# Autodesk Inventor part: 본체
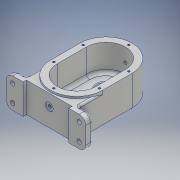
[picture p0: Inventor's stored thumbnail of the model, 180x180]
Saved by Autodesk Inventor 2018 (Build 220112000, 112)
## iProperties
Created: 2021-05
Part Number: 본체
Material: 알루미늄 6061
Document SubType Name: Modeling
Designer: Admin
Density: 2.7 g/cm^3
Appearance: 알루미늄 - 평지
Mass: 756.275 g
Surface Area: 582.942 cm^2
Volume: 280.102 cm^3
Author: Admin
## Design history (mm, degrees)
sketch "스케치1"
  geometry: L1 (-56, 0)-(56, 0) reference; L2 (0, -87.5)-(0, 87.5) reference; L3 (0, 22.5)-(0, -22.5); L4 (-40, 22.5)-(-40, -22.5); L5 (40, -22.5)-(40, 22.5); A1 r 40 centre (0, 22.5) between (40, 22.5) and (-40, 22.5); A2 r 40 centre (0, -22.5) between (-40, -22.5) and (40, -22.5); 2 further points
  constraints: 8 end point, 4 point on circle, 4 tangent, 2 centre point, 2 point on line, 1 coincident, 1 midpoint, 1 parallel
  dimensions: "d0" = 80 diameter of A2; "d1" = 45 distance of L5.start L5.end
extrude "돌출1" new body sketch "스케치1" distance "d2" = 49; taper "d3" = 0 deg
node "작업 평면1"
sketch "스케치2"
  geometry: L1 (61, -3)-(-61, -3); L2 (-61, -3)-(-61, -49); L3 (-61, -49)-(61, -49); L4 (61, -49)-(61, -3); L5 (-40, -49)-(40, -49) reference; L6 (85.4, 0)-(-85.4, 0) reference; L7 (0, -58.8)-(0, 9.8) reference; L8 (40, 0)-(-40, 0) reference; 2 further points
  constraints: 8 end point, 2 midpoint, 2 parallel, 1 horizontal, 1 perpendicular, 1 other
  dimensions: "d5" = 46 distance of L3.end L1.start; "d6" = 122 distance of L1.start L1.end
extrude "돌출2" join sketch "스케치2" distance "d7" = 10; taper "d8" = 0 deg
sketch "스케치3"
  geometry: L1 (-61, 3)-(61, 3) reference; L2 (-61, 49)-(-61, 3) reference; L3 (61, 49)-(-61, 49) reference; L4 (61, 3)-(61, 49) reference; L5 (0, 58.8)-(0, -9.8) reference; L6 (61, 49)-(-61, 49) reference; L7 (-40, 3)-(40, 3); L8 (40, 3)-(40, 49); L9 (40, 49)-(-40, 49); L10 (-40, 49)-(-40, 3); 1 further point
  constraints: 8 end point, 2 parallel, 2 point on line, 1 horizontal, 1 perpendicular, 1 other
  dimensions: "d9" = 80 distance between parallel lines of L8 L10
extrude "돌출3" join sketch "스케치3" distance "d10" = 37; taper "d11" = 0 deg
sketch "스케치4"
  geometry: L1 (-40, 22.5)-(-40, -22.5) reference; L2 (40, -22.5)-(40, 22.5) reference; L3 (0, 22.5)-(0, -22.5); L4 (-30, 22.5)-(-30, -22.5); L5 (30, -22.5)-(30, 22.5); A1 r 40 centre (0, -22.5) between (-40, -22.5) and (40, -22.5) reference; A2 r 40 centre (0, 22.5) between (40, 22.5) and (-40, 22.5) reference; A3 r 30 centre (0, 22.5) between (30, 22.5) and (-30, 22.5); A4 r 30 centre (0, -22.5) between (-30, -22.5) and (30, -22.5); 2 further points
  constraints: 8 end point, 4 point on circle, 4 tangent, 2 centre point, 1 midpoint, 1 parallel, 1 vertical
  dimensions: "d12" = 60 diameter of A4
extrude "돌출4" cut sketch "스케치4" distance "d13" = 41; taper "d14" = 0 deg
sketch "스케치5"
  geometry: L1 (-30, -22.5)-(-30, 22.5) reference; L2 (30, 22.5)-(30, -22.5) reference; C1 r 14 at (0, 22.5); C2 r 14 at (0, -22.5); A1 r 30 centre (0, -22.5) between (-30, -22.5) and (30, -22.5) reference; A2 r 30 centre (0, 22.5) between (30, 22.5) and (-30, 22.5) reference; 1 further point
  constraints: 2 centre point, 2 coincident
  dimensions: "d15" = 28 diameter of C1; "d16" = 28 diameter of C2
  node "투영된 루프3"
sketch "스케치6"
  geometry: L1 (40, -59.5)-(40, 22.5) reference; L2 (-40, 22.5)-(-40, -59.5) reference; L3 (-61, -59.5)-(-40, -59.5) reference; L4 (-61, -69.5)-(-61, -59.5) reference; L5 (-61, -69.5)-(61, -69.5) reference; L6 (61, -69.5)-(61, -59.5) reference; L7 (40, -59.5)-(61, -59.5) reference; L8 (85.4, 0)-(-85.4, 0) reference; L9 (0, -95.9)-(0, 88.9) reference; L10 (0, 22.5)-(0, -22.5); L11 (26, -22.5)-(26, -7.5); L12 (-26, -7.5)-(26, -7.5); L13 (-26, -7.5)-(-26, -22.5); A1 r 40 centre (0, 22.5) between (40, 22.5) and (-40, 22.5) reference; A2 r 26 centre (0, -22.5) between (-26, -22.5) and (26, -22.5); 2 further points
  constraints: 10 end point, 2 point on circle, 2 point on line, 2 tangent, 1 centre point, 1 coincident, 1 horizontal, 1 midpoint, 1 parallel
  dimensions: "d17" = 52 diameter of A2; "d19" = 30 distance from line of L12 A1.centre; "d20" = 47 distance from line of L5 L10.end; "d21" = 15 distance of L12.start L13.end
extrude "돌출5" join sketch "스케치6" distance "d22" = 11; taper "d23" = 0 deg
sketch "스케치7"
  geometry: L1 (-26, -22.5)-(-26, -7.5) reference; L2 (-26, -7.5)-(26, -7.5) reference; L3 (26, -7.5)-(26, -22.5) reference; L4 (40, -59.5)-(40, 22.5) reference; L5 (-40, 22.5)-(-40, -59.5) reference; L6 (-61, -59.5)-(-40, -59.5) reference; L7 (-61, -69.5)-(-61, -59.5) reference; L8 (-61, -69.5)-(61, -69.5) reference; L9 (61, -69.5)-(61, -59.5) reference; L10 (40, -59.5)-(61, -59.5) reference; L11 (85.4, 0)-(-85.4, 0) reference; L12 (0, -95.9)-(0, 88.9) reference; L13 (0, 22.5)-(0, -22.5); L14 (-26, 22.5)-(-26, -22.5); L15 (26, -22.5)-(26, 22.5); A1 r 26 centre (0, -22.5) between (-26, -22.5) and (26, -22.5) reference; A2 r 40 centre (0, 22.5) between (40, 22.5) and (-40, 22.5) reference; A3 r 26 centre (0, 22.5) between (26, 22.5) and (-26, 22.5); A4 r 26 centre (0, -22.5) between (-26, -22.5) and (26, -22.5); 2 further points
  constraints: 8 end point, 4 point on circle, 4 tangent, 2 centre point, 1 collinear, 1 midpoint, 1 parallel
  dimensions: "d24" = 52 diameter of A4
extrude "돌출6" join sketch "스케치7" distance "d25" = 8; taper "d26" = 0 deg
extrude "돌출7" cut sketch "스케치5" distance "d27" = 8; taper "d28" = 0 deg
sketch "스케치8"
  geometry: L1 (26, -7.5)-(-26, -7.5) reference; L2 (26, -7.5)-(26, 22.5) reference; L3 (-26, 22.5)-(-26, -7.5) reference; C1 r 14 at (0, 22.5); A1 r 26 centre (0, 22.5) between (26, 22.5) and (-26, 22.5) reference; 1 further point
  constraints: 1 centre point, 1 coincident
  dimensions: "d29" = 28 diameter of C1
extrude "돌출8" cut sketch "스케치8" distance "d30" = 4; taper "d31" = 0 deg
sketch "스케치9"
  geometry: C1 r 14 at (0, 0) reference; C2 r 11 at (0, 0); 1 further point
  constraints: 1 centre point, 1 coincident
  dimensions: "d32" = 22 diameter of C2
extrude "돌출9" cut sketch "스케치9" stored distance "d33" = 4; taper "d34" = 0 deg
sketch "스케치10"
  geometry: C1 r 14 at (0, 0) reference; C2 r 10 at (0, 0); 1 further point
  constraints: 1 centre point, 1 coincident
  dimensions: "d35" = 20 diameter of C2
extrude "돌출10" cut sketch "스케치10" distance "d36" = 4; taper "d37" = 0 deg
node "작업 평면2"
sketch "스케치11"
  geometry: L1 (0, -72)-(0, 12) reference; L2 (40, 0)-(-40, 0) reference; C1 r 6 at (0, -21); 1 further point
  constraints: 1 centre point, 1 point on line
  dimensions: "d39" = 12 diameter of C1; "d40" = 21 distance from line of L2 C1.centre
extrude "돌출11" join sketch "스케치11" stored distance "d41" = 4; taper "d42" = 0 deg
sketch "스케치12"
  geometry: L1 (-30, -22.5)-(-30, 22.5) reference; L2 (30, 22.5)-(30, -22.5) reference; L3 (-40, 22.5)-(-40, -22.5) reference; L4 (40, -22.5)-(40, 22.5) reference; L5 (-85.4, 0)-(85.4, 0) reference; L6 (0, -96.5)-(0, 92.5) reference; L7 (0, 22.5)-(0, -22.5); L8 (-35, 22.5)-(-35, -22.5); L9 (35, -22.5)-(35, 22.5); A1 r 30 centre (0, -22.5) between (-30, -22.5) and (30, -22.5) reference; A2 r 30 centre (0, 22.5) between (30, 22.5) and (-30, 22.5) reference; A3 r 40 centre (0, -22.5) between (-40, -22.5) and (40, -22.5) reference; A4 r 40 centre (0, 22.5) between (40, 22.5) and (-40, 22.5) reference; A5 r 35 centre (0, 22.5) between (35, 22.5) and (-35, 22.5); A6 r 35 centre (0, -22.5) between (-35, -22.5) and (35, -22.5); 8 further points
  constraints: 8 end point, 6 point on circle, 4 coincident, 4 tangent, 2 centre point, 1 collinear, 1 midpoint, 1 parallel
  dimensions: "d43" = 70 diameter of A6
hole "구멍1" sketch "스케치12" at (0, 57.5), (0, -57.5), (-35, 22.5), (35, 22.5), (35, -22.5), (-35, -22.5) diameter "d44" = 3.242; stored, may be unused: countersink angle "d48" = 90 deg, drill point angle "d50" = 118 deg; dims "d45" = 8, "d46" = 4, "d47" = 2, "d49" = 10
fillet "모깎기1" dims "d51" = 10, "d79" = 5, "d80" = 3, "d96" = 0.3
sketch "스케치13"
  geometry: L1 (-61, 39)-(-61, 13) reference; L2 (-51, 3)-(-40, 3) reference; L3 (-40, 3)-(-40, 49) reference; L4 (-40, 49)-(-51, 49) reference; L5 (51, 49)-(40, 49) reference; L6 (40, 49)-(40, 3) reference; L7 (40, 3)-(51, 3) reference; L8 (61, 13)-(61, 39) reference; C1 r 5.5 at (-51, 13); C2 r 5.5 at (-51, 39); C3 r 5.5 at (51, 13); C4 r 5.5 at (51, 39); A1 r 10 centre (-51, 39) between (-51, 49) and (-61, 39) reference; A2 r 10 centre (-51, 13) between (-61, 13) and (-51, 3) reference; A3 r 10 centre (51, 39) between (61, 39) and (51, 49) reference; A4 r 10 centre (51, 13) between (51, 3) and (61, 13) reference; 1 further point
  constraints: 4 centre point, 4 coincident
  dimensions: "d52" = 11 diameter of C1; "d53" = 11 diameter of C2; "d54" = 11 diameter of C3; "d55" = 11 diameter of C4
extrude "돌출12" cut sketch "스케치13" distance "d56" = 2; taper "d57" = 0 deg
sketch "스케치14"
  geometry: C1 r 5.5 at (0, 0) reference; C2 r 5.5 at (0, 26) reference; C3 r 5.5 at (102, 26) reference; C4 r 5.5 at (102, 0) reference; C5 r 3.3 at (0, 0); C6 r 3.3 at (0, 26); C7 r 3.3 at (102, 0); C8 r 3.3 at (102, 26); 1 further point
  constraints: 4 centre point, 4 coincident
  dimensions: "d58" = 6.6 diameter of C5; "d59" = 6.6 diameter of C6; "d60" = 6.6 diameter of C7; "d61" = 6.6 diameter of C8
extrude "돌출13" cut sketch "스케치14" stored distance "d62" = 0; taper "d63" = 0 deg
chamfer "모따기1" distance "d76" = 1; stored, may be unused: second distance "d77" = 2, angle "d78" = 45 deg
sketch "스케치18"
  geometry: L1 (0, -96.506)-(0, 92.534) reference; L2 (51, -62.5)-(51, -69.5) reference; L3 (43, -62.5)-(51, -62.5) reference; L4 (37, 22.5)-(37, -56.5) reference; L5 (-37, -56.5)-(-37, 22.5) reference; L6 (-51, -62.5)-(-43, -62.5) reference; L7 (-51, -69.5)-(-51, -62.5) reference; L8 (-51, -69.5)-(51, -69.5) reference; L9 (29, -22.5)-(29, 22.5) reference; L10 (-29, 22.5)-(-29, -22.5) reference; L11 (-51, -69.5)-(51, -69.5) reference; L12 (-35, -69.5)-(35, -69.5); L13 (35, -69.5)-(35, -64.5); L14 (35, -64.5)-(-35, -64.5); L15 (-35, -64.5)-(-35, -69.5); A1 r 37 centre (0, 22.5) between (37, 22.5) and (-37, 22.5) reference; A2 r 29 centre (0, -22.5) between (-29, -22.5) and (29, -22.5) reference; A3 r 29 centre (0, 22.5) between (29, 22.5) and (-29, 22.5) reference; A4 r 6 centre (43, -56.5) between (37, -56.5) and (43, -62.5) reference; A5 r 6 centre (-43, -56.5) between (-43, -62.5) and (-37, -56.5) reference; 1 further point
  constraints: 8 end point, 2 parallel, 1 horizontal, 1 perpendicular, 1 point on line, 1 other
  dimensions: "d81" = 5 distance between parallel lines of L12 L14; "d82" = 70 distance between parallel lines of L15 L13
extrude "돌출15" cut sketch "스케치18" stored distance "d83" = 1; taper "d84" = 0 deg
sketch "스케치19"
  geometry: L1 (0, 46)-(70, 46) reference; L2 (0, 0)-(0, 46) reference; L3 (70, 0)-(0, 0) reference; L4 (70, 0)-(70, 46) reference; L5 (75, 49)-(-5, 49) reference; L6 (35, -23)-(35, 61) reference; C1 r 6 at (35, 28); 1 further point
  constraints: 1 centre point, 1 point on line
  dimensions: "d85" = 12 diameter of C1; "d86" = 21 distance from line of L5 C1.centre
extrude "돌출16" cut sketch "스케치19" distance "d87" = 1; taper "d88" = 0 deg
sketch "스케치20"
  geometry: C1 r 6 at (0, 0) reference; 2 further points
  constraints: 1 coincident
hole "구멍3" sketch "스케치20" at (0, 0) diameter "d89" = 4.917; stored, may be unused: countersink angle "d93" = 90 deg, drill point angle "d95" = 118 deg; dims "d90" = 140, "d91" = 4, "d92" = 2, "d94" = 140
sketch "스케치21" dims "d97" = 40
  geometry: L1 (26, -7.5)-(-26, -7.5) reference; L2 (26, -7.5)-(26, 22.5) reference; L3 (-26, 22.5)-(-26, -7.5) reference; L4 (0, -96.506)-(0, 92.534) reference; C1 r 15 at (0, 22.5) reference; A1 r 26 centre (0, 22.5) between (26, 22.5) and (-26, 22.5) reference; 3 further points
  constraints: 1 coincident, 1 point on line, 1 vertical alignment, 2 other
hole "구멍4" sketch "스케치21" at (0, 42.5) diameter "d98" = 3.242; stored, may be unused: countersink angle "d102" = 90 deg, drill point angle "d104" = 118 deg; dims "d99" = 8, "d100" = 4, "d101" = 2, "d103" = 10
sketch "스케치22"
  geometry: L1 (0, -96.506)-(0, 92.534) reference; L2 (-51, -69.5)-(-35, -69.5) reference; 2 further points
  constraints: 1 point on line, 1 other
  dimensions: "d108" = 12 distance from line of L2 point (0, -57.5)
feature "엠보싱1" sketch "스케치22" dims "d109" = 0.5, "d110" = 0
node "솔리드1"
pattern_circular "원형 패턴1" dims angle "d106" = 360 deg
node "투영된 루프1"
node "투영된 루프2"
node "투영된 루프4"
node "투영된 루프5"
node "투영된 루프6"
node "투영된 루프7"
node "투영된 루프8"
node "투영된 루프9"
node "투영된 루프10"
node "투영된 루프11"
node "투영된 루프13"
node "투영된 루프14"
node "투영된 루프15"
other parameters: "d4" = -69.5, "d38" = 65.5
